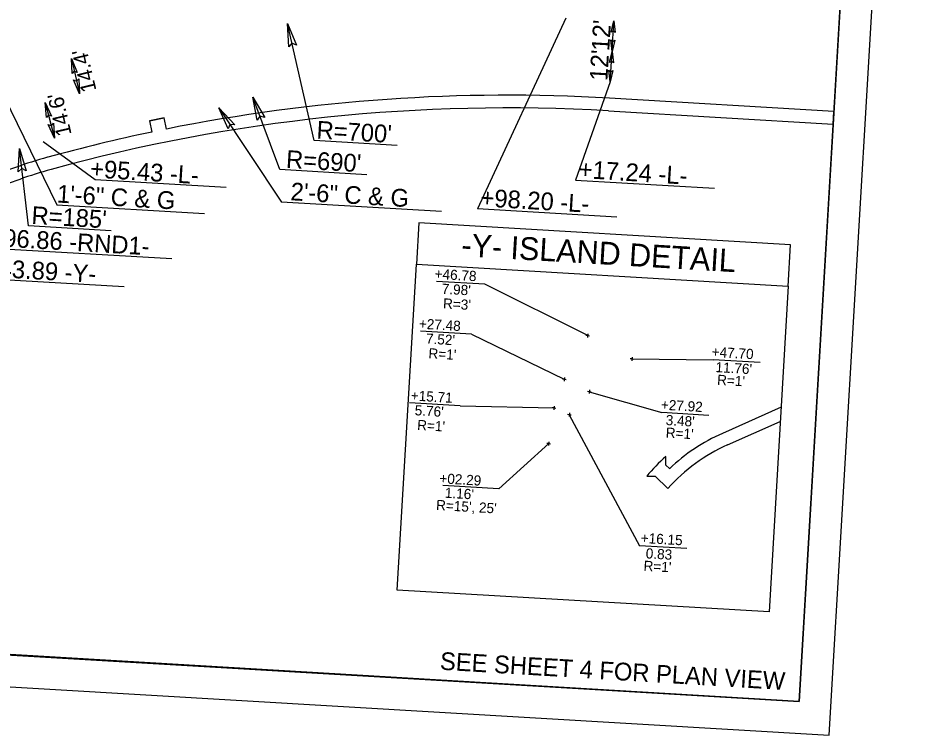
# Model space of a CAD drawing. Extents: x 2011491 to 2012372, y 444688 to 445287.
# Drawn here: x 2012019.7 to 2012371.9, y 444688.4 to 444971.3 of the extents above; entities that cross this region are included whole.
import ezdxf

# ---------------------------------------------------------------- set-up
doc = ezdxf.new("R2010")
doc.units = 0
for name, color, linetype in [('Old_Level_1', 7, 'Continuous'), ('Old_Level_10', 7, 'Continuous'), ('Prop Conc 4in Sidewalk', 7, 'Continuous'), ('Prop Dimension', 7, 'Continuous'), ('Prop Dimension Text', 7, 'Continuous'), ('Prop Shade Medium', 7, 'Continuous'), ('Prop Terminator CELL', 7, 'Continuous'), ('Sheet Clip Boundary CELL', 7, 'Continuous'), ('Sheet Plan And Profile CELL', 7, 'Continuous'), ('Sheet Plot Border Outside CELL', 7, 'Continuous')]:
    doc.layers.add(name, color=color, linetype=linetype)

msp = doc.modelspace()

# ---------------------------------------------------------------- linework, layer by layer
at = {"layer": 'Old_Level_1'}
for points in [[(2012176.9, 444874.09), (2012323.47, 444865.45), (2012324.43, 444881.78), (2012177.87, 444890.42)], [(2012176.9, 444874.09), (2012323.47, 444865.45), (2012315.89, 444736.97), (2012169.33, 444745.61)]]:
    msp.add_lwpolyline(points, close=True, dxfattribs=at)
at = {"layer": 'Prop Conc 4in Sidewalk'}
for radius, end in [(73.5, 133.5582), (68.5, 138.4074)]:
    msp.add_arc((2012327.29, 444740.21), radius, 113.9163, end, dxfattribs=at)
at = {"layer": 'Prop Dimension'}
for p, q in [((2012235.72, 444971.15), (2012201.01, 444895.95)), ((2012254.03, 444958.05), (2012254.73, 444970.03)), ((2012136.5, 444922.87), (2012126.03, 444969)), ((2012006.14, 444956.68), (2012035.03, 444897.56)), ((2012253.32, 444946.07), (2012254.03, 444958.05)), ((2012040.84, 444955.28), (2012043.99, 444941.27)), ((2012253.32, 444946.07), (2012239.62, 444907.31)), ((2012123, 444911.41), (2012112.39, 444939.93)), ((2012030.53, 444937.94), (2012034.19, 444923.77)), ((2012098.95, 444935.79), (2012123.6, 444898.63)), ((2012029.73, 444922.56), (2012050.23, 444907.49)), ((2012169.33, 444920.93), (2012136.5, 444922.87)), ((2012023.87, 444889.22), (2012020.31, 444919.69)), ((2012157.3, 444909.39), (2012123, 444911.41)), ((2012035.03, 444897.56), (2012093.29, 444894.12)), ((2012186.77, 444894.91), (2012123.6, 444898.63)), ((2012255.91, 444892.71), (2012201.01, 444895.95)), ((2012056.56, 444887.29), (2012023.87, 444889.22)), ((2012080.44, 444876.17), (2012009.29, 444880.37)), ((2012061.63, 444865.15), (2012007.49, 444868.35)), ((2012203.88, 444866.22), (2012184.74, 444867.34)), ((2012244.41, 444845.93), (2012203.88, 444866.22)), ((2012198.61, 444846.5), (2012178.52, 444847.69)), ((2012198.61, 444846.5), (2012235.18, 444828.73)), ((2012261.9, 444836.76), (2012293.85, 444836.43)), ((2012312.47, 444835.33), (2012293.85, 444836.43)), ((2012245.04, 444823.82), (2012273.58, 444815.6)), ((2012194.17, 444818.26), (2012174.08, 444819.44)), ((2012194.17, 444818.26), (2012231.11, 444817.44)), ((2012292.2, 444814.5), (2012273.58, 444815.6)), ((2012237.14, 444814.75), (2012264.83, 444763.08)), ((2012209.4, 444785.48), (2012229.02, 444803.35)), ((2012209.4, 444785.48), (2012187.33, 444786.78)), ((2012283.45, 444761.99), (2012264.83, 444763.08))]:
    msp.add_line(p, q, dxfattribs=at)
at = {"layer": 'Prop Dimension Text'}
for p, q in [((2012050.23, 444907.49), (2012101.88, 444904.44)), ((2012239.62, 444907.31), (2012294.39, 444904.09)), ((2012244.45, 444846.68), (2012244.36, 444845.18)), ((2012244.41, 444845.93), (2012243.66, 444845.97)), ((2012244.41, 444845.93), (2012245.16, 444845.88)), ((2012261.9, 444836.76), (2012261.15, 444836.8)), ((2012261.95, 444837.51), (2012261.86, 444836.01)), ((2012261.9, 444836.76), (2012262.65, 444836.71)), ((2012235.23, 444829.48), (2012235.14, 444827.98)), ((2012235.18, 444828.73), (2012234.43, 444828.78)), ((2012235.18, 444828.73), (2012235.93, 444828.69)), ((2012245.04, 444823.82), (2012244.29, 444823.87)), ((2012245.08, 444824.57), (2012244.99, 444823.08)), ((2012245.04, 444823.82), (2012245.79, 444823.78)), ((2012231.11, 444817.44), (2012230.36, 444817.49)), ((2012231.15, 444818.19), (2012231.06, 444816.7)), ((2012231.11, 444817.44), (2012231.86, 444817.4)), ((2012237.19, 444815.5), (2012237.1, 444814)), ((2012237.14, 444814.75), (2012236.39, 444814.79)), ((2012237.14, 444814.75), (2012237.89, 444814.7)), ((2012229.02, 444803.35), (2012228.27, 444803.39)), ((2012229.06, 444804.1), (2012228.97, 444802.6)), ((2012229.02, 444803.35), (2012229.76, 444803.3))]:
    msp.add_line(p, q, dxfattribs=at)
at = {"layer": 'Prop Shade Medium'}
for p, q in [((2012341.48, 444934.36), (2012252.94, 444939.58)), ((2012252.64, 444934.59), (2012341.18, 444929.37)), ((2012077.46, 444931.84), (2012071.58, 444930.63)), ((2012071.59, 444930.63), (2012077.46, 444931.84)), ((2012078.37, 444927.43), (2012077.46, 444931.84)), ((2012341.18, 444929.37), (2012341.48, 444934.36)), ((2012071.59, 444930.63), (2012072.49, 444926.23)), ((2012320.65, 444817.67), (2012297.5, 444807.4)), ((2012299.52, 444802.83), (2012320.32, 444812.05)), ((2012275.21, 444794.87), (2012275.16, 444798.23)), ((2012276.65, 444793.48), (2012275.21, 444794.87)), ((2012267.68, 444790.51), (2012271.03, 444790.56)), ((2012271.03, 444790.56), (2012276.06, 444785.69))]:
    msp.add_line(p, q, dxfattribs=at)
for centre, radius, start, end in [((2012212.72, 444257.26), 683.5, 86.62643, 101.33591), ((2012212.72, 444257.26), 678.5, 86.62643, 105.37852), ((2012212.72, 444257.26), 683.5, 101.83883, 105.37852), ((2012078.79, 444744.18), 178.5, 105.3785, 113.9163), ((2012078.79, 444744.18), 173.5, 105.3785, 113.9163), ((2012327.29, 444740.21), 73.5, 113.9163, 133.5582), ((2012327.29, 444740.21), 68.5, 113.9163, 138.4074), ((2012327.29, 444740.21), 78, 131.9465, 139.8471)]:
    msp.add_arc(centre, radius, start, end, dxfattribs=at)
at = {"layer": 'Prop Terminator CELL'}
for points in [[(2012253.69, 444965.58), (2012254.73, 444970.03), (2012255.26, 444965.46), (2012254.5, 444966.08)], [(2012126.51, 444959.88), (2012126.03, 444969), (2012129.59, 444960.53), (2012127.78, 444961.3)], [(2012255.06, 444962.49), (2012254.03, 444958.05), (2012253.49, 444962.61), (2012254.26, 444961.99)], [(2012252.99, 444953.6), (2012254.03, 444958.05), (2012254.56, 444953.48), (2012253.79, 444954.1)], [(2012041.14, 444949.35), (2012040.84, 444955.28), (2012043.14, 444949.77), (2012041.96, 444950.27)], [(2012254.36, 444950.52), (2012253.32, 444946.07), (2012252.79, 444950.63), (2012253.55, 444950.01)], [(2012043.69, 444947.2), (2012043.99, 444941.27), (2012041.68, 444946.78), (2012042.86, 444946.28)], [(2012114.07, 444930.96), (2012112.39, 444939.93), (2012117.04, 444932.01), (2012115.14, 444932.53)], [(2012031.02, 444932.03), (2012030.53, 444937.94), (2012033.01, 444932.51), (2012031.82, 444932.97)], [(2012102.64, 444927.44), (2012098.95, 444935.79), (2012105.29, 444929.14), (2012103.32, 444929.21)], [(2012033.7, 444929.69), (2012034.19, 444923.77), (2012031.71, 444929.21), (2012032.91, 444928.74)], [(2012019.81, 444910.58), (2012020.31, 444919.69), (2012022.95, 444910.89), (2012021.22, 444911.85)]]:
    msp.add_lwpolyline(points, close=True, dxfattribs=at)
at = {"layer": 'Sheet Clip Boundary CELL'}
for points in [[(2012353.36, 445134.84), (2012253.51, 445140.73), (2012256.91, 445198.29), (2012157.05, 445204.18), (2012159.02, 445237.47), (2011610.02, 445269.83), (2011579.13, 444745.74), (2012327.83, 444701.6)], [(2011579.79, 444746.22), (2011610.64, 445269.52), (2012158.83, 445237.2), (2012156.87, 445204), (2012256.73, 445198.11), (2012253.34, 445140.51), (2012353.28, 445134.62), (2012327.76, 444701.71)]]:
    msp.add_lwpolyline(points, close=True, dxfattribs=at)
at = {"layer": 'Sheet Plan And Profile CELL'}
msp.add_lwpolyline([(2012358.72, 445225.69), (2011610.02, 445269.83), (2011579.13, 444745.74), (2012327.83, 444701.6)], close=True, dxfattribs=at)
at = {"layer": 'Sheet Plot Border Outside CELL'}
msp.add_lwpolyline([(2011491.04, 444738.41), (2012339.57, 444688.39), (2012371.93, 445237.44), (2011523.41, 445287.46)], close=True, dxfattribs=at)

# ---------------------------------------------------------------- texts
at = {"layer": 'Old_Level_10'}
for s, p in [('+46.78', (2012183.96, 444868.37)), ("7.98'", (2012186.76, 444862.47)), ("R=3'", (2012187.26, 444856.69)), ('+27.48', (2012177.74, 444848.71)), ("7.52'", (2012180.54, 444842.81)), ("R=1'", (2012181.52, 444837.01)), ('+47.70', (2012293.21, 444837.61)), ("11.76'", (2012294.71, 444831.57)), ("R=1'", (2012295.34, 444826.57)), ('+15.71', (2012174.56, 444820.39)), ("5.76'", (2012176.09, 444814.56)), ('+27.92', (2012273.16, 444816.77)), ("R=1'", (2012177.07, 444808.76)), ("3.48'", (2012275.07, 444810.71)), ("R=1'", (2012275.08, 444805.74)), ('+02.29', (2012185.83, 444787.73)), ("1.16'", (2012187.99, 444782.02)), ("R=15', 25'", (2012184.53, 444777.21)), ('+16.15', (2012265.23, 444764.21)), ('0.83', (2012267.2, 444758.14)), ("R=1'", (2012266.33, 444753.23))]:
    msp.add_text(s, height=4, rotation=356.6264, dxfattribs=at).set_placement(p)
at = {"layer": 'Prop Dimension'}
for s, height, p in [('-Y- ISLAND DETAIL', 9, (2012194.41, 444877.33)), ('SEE SHEET 4 FOR PLAN VIEW', 7, (2012186, 444714.21))]:
    msp.add_text(s, height=height, rotation=356.6264, dxfattribs=at).set_placement(p)
at = {"layer": 'Prop Dimension Text'}
for s, height, rotation, p in [("12'", 7, 86.6264, (2012252.88, 444958.05)), ("14.4'", 6, 103.4479, (2012050.74, 444942.72)), ("12'", 7, 86.6264, (2012252.13, 444946.25)), ("14.6'", 6, 102.8719, (2012040.94, 444925.36)), ("R=700'", 7, 356.6264, (2012137.34, 444923.67)), ("R=690'", 7, 356.6264, (2012125.31, 444912.12)), ('+95.43 -L-', 7, 356.3956, (2012048.04, 444908.39)), ('+17.24 -L-', 7, 356.4026, (2012240.68, 444908.18)), ('1\'-6" C & G', 7, 356.6264, (2012034.95, 444898.45)), ('2\'-6" C & G', 7, 356.6264, (2012127.08, 444899.35)), ('+98.20 -L-', 7, 356.6264, (2012201.98, 444896.95)), ("R=185'", 7, 356.6264, (2012024.94, 444890)), ('+96.86 -RND1-', 7, 356.6264, (2012008.34, 444881.35)), ('+43.89 -Y-', 7, 356.6264, (2012006.54, 444869.33))]:
    msp.add_text(s, height=height, rotation=rotation, dxfattribs=at).set_placement(p)

doc.saveas('drawing.dxf')
